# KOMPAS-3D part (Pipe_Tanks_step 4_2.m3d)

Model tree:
1. X Axis
2. Y Axis
3. Z Axis  (labels: Pipe Dn 150; Valve Dy 150)
     Òîëùèíà ñòåíêè 1 = 1

Referenced files in C:\Documents and Settings\kashirsky\Мои документы\Camtasia Studio\Pipelines3D\Tanks\: Tanks_step 4.a3d
Referenced files in C:\Program Files\ASCON\KOMPAS-3D V10\Libs\Piping\LOAD\: Piping_C_Pipe_150_1000.m3d
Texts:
  Pipe Dn 150
  Steel ASTM A295
  Three Point Plane
  Plane at Angle
  Line and Point Plane
  Axis through Two Vertices
  Axis of Feature
  Axis of Conical Surface
  Axis through Edge
  Trim by Surface
  Trim by Sketch
  Feature with No History
  Intersection Axis of Two Planes
  Two Line Plane
  Line and Face Plane
  Bend by line
  Hole in sheet body
  Cut in sheet body
  Point in CM
  Linear Dimension from Line to Point
  Surface Finish Symbol
  Geometric Tolerance Symbol
  Leader #1
  Leader #2
  Leader #3
  Shape Deviations and Datum
  Node point number
  Mark of coordination axis
  Node point designation
  Mark/Reference designation with leader
  Mark/reference designation on line
  Mark/Reference designation without leader
  Valve Dy 150
  Plane of section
